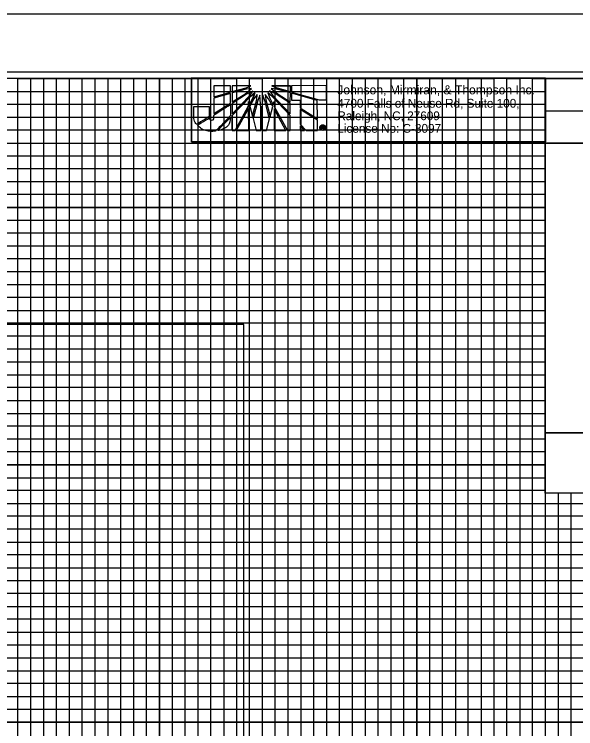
# Model space of a CAD drawing. Extents: x 1624665 to 1626605, y 896887 to 897987.
# Drawn here: x 1625926 to 1626144.2, y 897709.9 to 897987.4 of the extents above; entities that cross this region are included whole.
import ezdxf

# ---------------------------------------------------------------- set-up
doc = ezdxf.new("R2010")
doc.units = 0
for name, color, linetype in [('Default', 7, 'Continuous'), ('Prop PHM Black Shape', 7, 'Continuous'), ('Scratch_Level_1', 7, 'Continuous'), ('Sheet Cutting Line CELL', 7, 'Continuous'), ('Sheet DOT Grid CELL', 7, 'Continuous'), ('Sheet Plot Border Inside CELL', 7, 'Continuous'), ('Sheet Plot Border Outside CELL', 7, 'Continuous'), ('Sheet Profile CELL', 7, 'Continuous'), ('Sheet Profile Grid Major CELL', 7, 'Continuous'), ('Sheet Profile Grid Middle CELL', 7, 'Continuous'), ('Sheet Profile Grid Minor CELL', 7, 'Continuous'), ('Sheet Sticker Exception Certification CELL', 7, 'Continuous')]:
    doc.layers.add(name, color=color, linetype=linetype)

msp = doc.modelspace()

# ---------------------------------------------------------------- linework, layer by layer
at = {"layer": 'Default'}
for p, q in [((1626010.05, 897959.66), (1626003.61, 897959.66)), ((1626003.61, 897959.66), (1626003.62, 897955.39)), ((1626010.05, 897957.18), (1626010.05, 897959.66)), ((1626017.96, 897959.7), (1626010.72, 897959.69)), ((1626010.72, 897959.69), (1626010.72, 897957.39)), ((1626016.12, 897958.88), (1626017.96, 897959.7)), ((1626033.3, 897959.68), (1626026.16, 897959.71)), ((1626026.16, 897959.71), (1626027.97, 897958.86)), ((1626033.3, 897957.37), (1626033.3, 897959.68)), ((1626047.33, 897959.73), (1626033.8, 897959.71)), ((1626033.8, 897959.71), (1626033.8, 897957.23)), ((1626047.33, 897954.18), (1626047.33, 897959.73)), ((1626003.62, 897955.39), (1626010.05, 897957.18)), ((1626010.05, 897956.71), (1626003.62, 897954.9)), ((1626010.06, 897952.98), (1626010.05, 897956.71)), ((1626010.72, 897957.39), (1626016.12, 897958.88)), ((1626016.12, 897958.38), (1626010.72, 897956.89)), ((1626010.72, 897956.89), (1626010.72, 897953.41)), ((1626015.55, 897956.47), (1626018.22, 897958.64)), ((1626018.22, 897958.64), (1626016.12, 897958.38)), ((1626018.75, 897957.64), (1626016.3, 897956.4)), ((1626017.51, 897955.9), (1626018.75, 897957.64)), ((1626019.49, 897956.87), (1626017.79, 897955.55)), ((1626018.71, 897954.8), (1626019.49, 897956.87)), ((1626024.49, 897956.87), (1626025.27, 897954.81)), ((1626026.2, 897955.55), (1626024.49, 897956.87)), ((1626025.24, 897957.65), (1626026.48, 897955.87)), ((1626027.73, 897956.41), (1626025.24, 897957.65)), ((1626025.8, 897958.64), (1626028.5, 897956.44)), ((1626027.79, 897958.39), (1626025.8, 897958.64)), ((1626033.3, 897956.88), (1626027.79, 897958.39)), ((1626027.97, 897958.86), (1626033.3, 897957.37)), ((1626033.26, 897953.47), (1626033.3, 897956.88)), ((1626033.8, 897957.23), (1626033.8, 897957.15)), ((1626033.8, 897957.15), (1626044.45, 897954.18)), ((1626033.8, 897956.77), (1626033.8, 897956.73)), ((1626043.77, 897953.93), (1626033.8, 897956.77)), ((1626033.8, 897956.73), (1626033.8, 897954.14)), ((1626003.62, 897954.9), (1626003.62, 897948.9)), ((1626010.72, 897953.41), (1626015.55, 897956.47)), ((1626016.3, 897956.4), (1626010.73, 897952.84)), ((1626010.73, 897948.83), (1626017.51, 897955.9)), ((1626017.79, 897955.55), (1626010.73, 897948.15)), ((1626017.36, 897952.35), (1626018.71, 897954.8)), ((1626019.15, 897954.66), (1626017.54, 897951.75)), ((1626018.58, 897947.88), (1626020.24, 897954.31)), ((1626020.6, 897953.95), (1626018.79, 897946.99)), ((1626020.42, 897956.29), (1626019.15, 897954.66)), ((1626020.24, 897954.31), (1626020.42, 897956.29)), ((1626021.48, 897956.01), (1626020.6, 897953.95)), ((1626021.76, 897950.93), (1626021.48, 897956.01)), ((1626022.54, 897956.01), (1626022.22, 897950.93)), ((1626023.39, 897953.95), (1626022.54, 897956.01)), ((1626025.25, 897946.89), (1626023.39, 897953.95)), ((1626023.57, 897956.3), (1626023.79, 897954.24)), ((1626024.82, 897954.66), (1626023.57, 897956.3)), ((1626023.79, 897954.24), (1626025.46, 897947.74)), ((1626026.49, 897951.65), (1626024.82, 897954.66)), ((1626025.27, 897954.81), (1626026.66, 897952.25)), ((1626033.27, 897948.11), (1626026.2, 897955.55)), ((1626026.48, 897955.87), (1626033.26, 897948.77)), ((1626033.26, 897952.89), (1626027.73, 897956.41)), ((1626028.5, 897956.44), (1626033.26, 897953.47)), ((1626033.8, 897954.14), (1626037.1, 897954.14)), ((1626037.1, 897954.14), (1626037.11, 897951.05)), ((1626043.78, 897946.83), (1626043.77, 897953.93)), ((1626044.45, 897954.18), (1626047.33, 897954.18)), ((1626003.62, 897948.9), (1626010.06, 897952.98)), ((1626010.73, 897952.84), (1626010.73, 897948.83)), ((1626011.8, 897942.31), (1626017.05, 897951.82)), ((1626017.05, 897951.82), (1626017.04, 897953.52)), ((1626017.04, 897953.52), (1626017.36, 897952.35)), ((1626017.54, 897951.75), (1626018.58, 897947.88)), ((1626025.46, 897947.74), (1626026.49, 897951.65)), ((1626026.66, 897952.25), (1626026.98, 897953.53)), ((1626026.98, 897953.53), (1626026.99, 897951.65)), ((1626026.99, 897951.65), (1626032.13, 897942.33)), ((1626033.26, 897948.77), (1626033.26, 897952.89)), ((1626017.05, 897950.89), (1626012.3, 897942.31)), ((1626017.1, 897942.31), (1626017.05, 897950.89)), ((1626021.77, 897942.35), (1626021.76, 897950.93)), ((1626022.22, 897950.93), (1626022.23, 897942.35)), ((1626031.6, 897942.36), (1626026.99, 897950.72)), ((1626026.99, 897950.72), (1626026.99, 897942.35)), ((1626037.11, 897951.05), (1626043.78, 897946.83)), ((1626037.11, 897950.52), (1626037.11, 897944.76)), ((1626043.78, 897946.33), (1626037.11, 897950.52)), ((1626010.73, 897948.15), (1626010.73, 897942.31)), ((1626018.79, 897946.99), (1626020.01, 897942.35)), ((1626024.01, 897942.35), (1626025.25, 897946.89)), ((1626033.27, 897942.33), (1626033.27, 897948.11)), ((1626043.78, 897942.34), (1626043.78, 897946.33)), ((1626037.11, 897944.76), (1626039.42, 897942.33)), ((1626038.78, 897942.33), (1626037.11, 897944.14)), ((1626037.11, 897944.14), (1626037.12, 897942.33)), ((1626045.48, 897942.95), (1626045.48, 897943.93)), ((1626045.48, 897943.93), (1626045.88, 897943.93)), ((1626045.7, 897942.95), (1626045.48, 897942.95)), ((1626045.88, 897943.74), (1626045.7, 897943.74)), ((1626045.7, 897943.74), (1626045.7, 897943.51)), ((1626045.7, 897943.51), (1626045.88, 897943.51)), ((1626045.88, 897943.33), (1626045.7, 897943.33)), ((1626045.7, 897943.33), (1626045.7, 897942.95)), ((1626045.88, 897944.51), (1626045.88, 897944.31)), ((1626045.88, 897944.31), (1626045.88, 897944.51)), ((1626045.88, 897943.93), (1626045.88, 897943.74)), ((1626045.88, 897943.74), (1626045.88, 897943.93)), ((1626045.88, 897943.93), (1626045.94, 897943.93)), ((1626045.91, 897943.74), (1626045.88, 897943.74)), ((1626045.88, 897943.51), (1626045.88, 897943.33)), ((1626045.88, 897943.33), (1626045.88, 897943.51)), ((1626045.88, 897943.51), (1626045.89, 897943.51)), ((1626045.89, 897943.33), (1626045.88, 897943.33)), ((1626010.73, 897942.31), (1626011.8, 897942.31)), ((1626012.3, 897942.31), (1626017.1, 897942.31)), ((1626020.01, 897942.35), (1626021.77, 897942.35)), ((1626022.23, 897942.35), (1626024.01, 897942.35)), ((1626026.99, 897942.35), (1626031.6, 897942.36)), ((1626032.13, 897942.33), (1626033.27, 897942.33)), ((1626037.12, 897942.33), (1626038.78, 897942.33)), ((1626039.42, 897942.33), (1626043.78, 897942.34)), ((1626045.88, 897942.56), (1626045.88, 897942.35)), ((1626045.88, 897942.35), (1626045.88, 897942.56)), ((1626045.88, 897942.56), (1626045.89, 897942.56)), ((1626045.89, 897942.35), (1626045.88, 897942.35))]:
    msp.add_line(p, q, dxfattribs=at)
for points in [[(1625994.91, 897937.88), (1626132.43, 897937.87), (1626132.44, 897962.69), (1625994.91, 897962.7)], [(1626026.16, 897959.71), (1626033.3, 897959.68), (1626033.3, 897957.37), (1626027.97, 897958.86)], [(1626010.73, 897942.31), (1626010.73, 897948.15), (1626017.79, 897955.55), (1626019.49, 897956.87), (1626018.93, 897955.24), (1626017.36, 897952.35), (1626017.04, 897953.52), (1626017.05, 897951.82), (1626011.8, 897942.31)]]:
    msp.add_lwpolyline(points, close=True, dxfattribs=at)
for points in [[(1626003.62, 897955.39), (1626010.05, 897957.18), (1626010.05, 897959.66), (1626003.61, 897959.66), (1626003.62, 897955.39)], [(1626016.12, 897958.88), (1626017.96, 897959.7), (1626010.72, 897959.69), (1626010.72, 897957.39), (1626016.12, 897958.88)], [(1626027.97, 897958.86), (1626033.3, 897957.37), (1626033.3, 897959.68), (1626026.16, 897959.71), (1626027.97, 897958.86)], [(1626047.33, 897959.73), (1626033.8, 897959.71), (1626033.8, 897957.23), (1626033.8, 897957.15), (1626044.45, 897954.18), (1626047.33, 897954.18), (1626047.33, 897959.73)], [(1626003.62, 897948.9), (1626010.06, 897952.98), (1626010.05, 897956.71), (1626003.62, 897954.9), (1626003.62, 897948.9)], [(1626010.72, 897956.89), (1626010.72, 897953.41), (1626015.55, 897956.47), (1626018.22, 897958.64), (1626016.12, 897958.38), (1626010.72, 897956.89)], [(1626010.73, 897952.84), (1626010.73, 897948.83), (1626017.51, 897955.9), (1626018.75, 897957.64), (1626016.3, 897956.4), (1626010.73, 897952.84)], [(1626019.49, 897956.87), (1626017.79, 897955.55), (1626010.73, 897948.15), (1626010.73, 897942.31), (1626011.8, 897942.31), (1626017.05, 897951.82), (1626017.04, 897953.52), (1626017.36, 897952.35), (1626018.71, 897954.8), (1626019.49, 897956.87)], [(1626024.49, 897956.87), (1626025.27, 897954.81), (1626026.66, 897952.25), (1626026.98, 897953.53), (1626026.99, 897951.65), (1626032.13, 897942.33), (1626033.27, 897942.33), (1626033.27, 897948.11), (1626026.2, 897955.55), (1626024.49, 897956.87)], [(1626025.24, 897957.65), (1626026.48, 897955.87), (1626033.26, 897948.77), (1626033.26, 897952.89), (1626027.73, 897956.41), (1626025.24, 897957.65)], [(1626025.8, 897958.64), (1626028.5, 897956.44), (1626033.26, 897953.47), (1626033.3, 897956.88), (1626027.79, 897958.39), (1626025.8, 897958.64)], [(1626033.8, 897956.77), (1626033.8, 897956.73), (1626033.8, 897954.14), (1626037.1, 897954.14), (1626037.11, 897951.05), (1626043.78, 897946.83), (1626043.77, 897953.93), (1626033.8, 897956.77)], [(1626020.42, 897956.29), (1626019.15, 897954.66), (1626017.54, 897951.75), (1626018.58, 897947.88), (1626020.24, 897954.31), (1626020.42, 897956.29)], [(1626020.6, 897953.95), (1626018.79, 897946.99), (1626020.01, 897942.35), (1626021.77, 897942.35), (1626021.76, 897950.93), (1626021.48, 897956.01), (1626020.6, 897953.95)], [(1626022.54, 897956.01), (1626022.22, 897950.93), (1626022.23, 897942.35), (1626024.01, 897942.35), (1626025.25, 897946.89), (1626023.39, 897953.95), (1626022.54, 897956.01)], [(1626023.57, 897956.3), (1626023.79, 897954.24), (1626025.46, 897947.74), (1626026.49, 897951.65), (1626024.82, 897954.66), (1626023.57, 897956.3)], [(1626012.3, 897942.31), (1626017.1, 897942.31), (1626017.05, 897950.89), (1626012.3, 897942.31)], [(1626026.99, 897942.35), (1626031.6, 897942.36), (1626026.99, 897950.72), (1626026.99, 897942.35)], [(1626037.11, 897950.52), (1626037.11, 897944.76), (1626039.42, 897942.33), (1626043.78, 897942.34), (1626043.78, 897946.33), (1626037.11, 897950.52), (1626037.11, 897950.52)], [(1626037.12, 897942.33), (1626037.12, 897942.33), (1626038.78, 897942.33), (1626037.11, 897944.14), (1626037.12, 897942.33)], [(1626046.31, 897943.18), (1626046.31, 897943.13), (1626046.32, 897943.09), (1626046.32, 897943.05), (1626046.35, 897942.95), (1626046.14, 897942.95)]]:
    msp.add_lwpolyline(points, dxfattribs=at)
for points, degree in [([(1626001.77, 897951.66), (1626001.77, 897951.66), (1625995.82, 897951.65), (1625995.82, 897951.65), (1625995.82, 897951.65), (1625995.82, 897947.92), (1625995.82, 897947.92), (1625995.82, 897947.92), (1625995.82, 897947.53), (1625995.82, 897947.53), (1625995.82, 897946.36), (1625996.2, 897945.44), (1625996.88, 897944.66), (1625996.88, 897944.66), (1626001.78, 897947.64), (1626001.78, 897947.72), (1626001.78, 897947.72), (1626001.77, 897951.66), (1626001.77, 897951.66)], 3), ([(1626002.7, 897946.29), (1626002.32, 897946.29), (1626001.99, 897946.51), (1626001.85, 897947.22), (1626001.85, 897947.22), (1625997.23, 897944.36), (1625997.23, 897944.36), (1625998.66, 897942.86), (1626000.93, 897941.97), (1626002.85, 897941.97), (1626003.35, 897941.97), (1626003.74, 897942.02), (1626004.27, 897942.12), (1626004.27, 897942.12), (1626010.06, 897948.12), (1626010.06, 897948.12), (1626010.06, 897948.12), (1626010.06, 897952.45), (1626010.06, 897952.45), (1626010.06, 897952.45), (1626003.62, 897948.36), (1626003.62, 897948.36), (1626003.63, 897946.73), (1626003.23, 897946.3), (1626002.7, 897946.29)], 3), ([(1626002.7, 897946.29), (1626002.32, 897946.29), (1626001.99, 897946.51), (1626001.85, 897947.22), (1626001.85, 897947.22), (1625997.23, 897944.36), (1625997.23, 897944.36), (1625998.66, 897942.86), (1626000.93, 897941.97), (1626002.85, 897941.97), (1626003.35, 897941.97), (1626003.74, 897942.02), (1626004.27, 897942.12), (1626004.27, 897942.12), (1626010.06, 897948.12), (1626010.06, 897948.12), (1626010.06, 897948.12), (1626010.06, 897952.45), (1626010.06, 897952.45), (1626010.06, 897952.45), (1626003.62, 897948.36), (1626003.62, 897948.36), (1626003.63, 897946.73), (1626003.23, 897946.3), (1626002.7, 897946.29)], 3), ([(1626010.06, 897947.44), (1626010.06, 897947.44), (1626005.05, 897942.26), (1626005.05, 897942.26), (1626007.51, 897942.87), (1626009.95, 897944.5), (1626010.06, 897947.44)], 3), ([(1626045.88, 897942.35), (1626045.59, 897942.35), (1626045.33, 897942.45), (1626045.11, 897942.67), (1626044.9, 897942.87), (1626044.79, 897943.13), (1626044.79, 897943.44), (1626044.79, 897943.74), (1626044.9, 897944), (1626045.11, 897944.2), (1626045.33, 897944.4), (1626045.58, 897944.51), (1626045.88, 897944.51)], 3), ([(1626045.88, 897944.31), (1626045.64, 897944.31), (1626045.43, 897944.22), (1626045.26, 897944.06), (1626045.09, 897943.89), (1626045, 897943.68), (1626045, 897943.44), (1626045, 897943.2), (1626045.09, 897942.98), (1626045.26, 897942.81), (1626045.43, 897942.64), (1626045.64, 897942.56), (1626045.88, 897942.56)], 3), ([(1626045.88, 897944.51), (1626046.18, 897944.51), (1626046.44, 897944.4), (1626046.66, 897944.2), (1626046.87, 897944), (1626046.98, 897943.74), (1626046.98, 897943.44)], 3), ([(1626045.89, 897942.56), (1626046.13, 897942.56), (1626046.34, 897942.64), (1626046.51, 897942.81), (1626046.68, 897942.98), (1626046.77, 897943.2), (1626046.77, 897943.44), (1626046.77, 897943.68), (1626046.68, 897943.89), (1626046.51, 897944.06), (1626046.34, 897944.23), (1626046.13, 897944.31), (1626045.88, 897944.31)], 3), ([(1626045.89, 897943.51), (1626046.03, 897943.51), (1626046.1, 897943.55), (1626046.1, 897943.63), (1626046.1, 897943.71), (1626046.04, 897943.74), (1626045.91, 897943.74)], 3), ([(1626046.98, 897943.44), (1626046.98, 897943.13), (1626046.87, 897942.88), (1626046.67, 897942.66), (1626046.45, 897942.45), (1626046.19, 897942.35), (1626045.89, 897942.35)], 3), ([(1626046.06, 897943.3), (1626046.03, 897943.31), (1626045.98, 897943.33), (1626045.89, 897943.33)], 2), ([(1626045.94, 897943.93), (1626046.19, 897943.93), (1626046.32, 897943.83), (1626046.32, 897943.64), (1626046.32, 897943.55), (1626046.28, 897943.47), (1626046.2, 897943.42)], 3), ([(1626046.14, 897942.95), (1626046.11, 897943), (1626046.1, 897943.05), (1626046.1, 897943.13), (1626046.1, 897943.21), (1626046.09, 897943.27), (1626046.06, 897943.3)], 3), ([(1626046.2, 897943.42), (1626046.27, 897943.38), (1626046.3, 897943.3), (1626046.31, 897943.18)], 2)]:
    msp.add_open_spline(points, degree=degree, dxfattribs=at)
at = {"layer": 'Prop PHM Black Shape'}
msp.add_lwpolyline([(1625994.91, 897962.7), (1626132.43, 897962.7), (1626132.43, 897937.87), (1625994.91, 897937.87)], close=True, dxfattribs=at)
at = {"layer": 'Scratch_Level_1'}
msp.add_lwpolyline([(1625682.2, 897612.11), (1626015.27, 897612.11), (1626015.27, 897866.93), (1625682.2, 897866.93)], close=True, dxfattribs=at)
at = {"layer": 'Sheet Cutting Line CELL'}
msp.add_line((1626349.4, 897987.44), (1624665.4, 897987.44), dxfattribs=at)
at = {"layer": 'Sheet DOT Grid CELL'}
for p, q in [((1625932.4, 897462.44), (1625932.4, 897962.44)), ((1625982.4, 897462.44), (1625982.4, 897962.44)), ((1626032.4, 897462.44), (1626032.4, 897962.44)), ((1626082.4, 897462.44), (1626082.4, 897962.44)), ((1626132.35, 897912.44), (1624832.4, 897912.44)), ((1626132.35, 897862.44), (1624832.4, 897862.44)), ((1626132.4, 897462.44), (1626132.4, 897824.89)), ((1626132.4, 897812.44), (1624832.4, 897812.44)), ((1626332.4, 897762.44), (1624832.4, 897762.44)), ((1626332.4, 897712.44), (1624832.4, 897712.44))]:
    msp.add_line(p, q, dxfattribs=at)
at = {"layer": 'Sheet Plot Border Inside CELL'}
msp.add_lwpolyline([(1624678.4, 896909.89), (1626344.9, 896909.89), (1626344.9, 897964.99), (1624678.4, 897964.99)], close=True, dxfattribs=at)
at = {"layer": 'Sheet Plot Border Outside CELL'}
msp.add_lwpolyline([(1624665.4, 896887.44), (1626349.4, 896887.44), (1626349.4, 897987.44), (1624665.4, 897987.44)], close=True, dxfattribs=at)
at = {"layer": 'Sheet Profile CELL'}
msp.add_line((1626132.35, 897949.89), (1626332.4, 897949.89), dxfattribs=at)
for points in [[(1626332.4, 897962.44), (1624832.4, 897962.44), (1624832.4, 896912.44), (1626332.4, 896912.44)], [(1626132.35, 897962.44), (1626332.4, 897962.44), (1626332.4, 897937.39), (1626132.35, 897937.39)], [(1626132.35, 897937.39), (1626232.4, 897937.39), (1626232.4, 897824.89), (1626132.35, 897824.89)]]:
    msp.add_lwpolyline(points, close=True, dxfattribs=at)
at = {"layer": 'Sheet Profile Grid Major CELL'}
for points in [[(1625582.4, 897462.44), (1625632.4, 897462.44), (1625632.4, 897962.44), (1625682.4, 897962.44), (1625682.4, 897462.44), (1625732.4, 897462.44), (1625732.4, 897962.44), (1625782.4, 897962.44), (1625782.4, 897462.44), (1625832.4, 897462.44), (1625832.4, 897962.44), (1625882.4, 897962.44), (1625882.4, 897462.44), (1625932.4, 897462.44), (1625932.4, 897962.44), (1625982.4, 897962.44), (1625982.4, 897462.44), (1626032.4, 897462.44), (1626032.4, 897962.44), (1626082.4, 897962.44), (1626082.4, 897462.44), (1626132.4, 897462.44), (1626132.4, 897962.44), (1626158.7, 897962.44)], [(1624832.4, 897912.44), (1626132.4, 897912.44)], [(1626132.4, 897862.44), (1624832.4, 897862.44), (1624832.4, 897812.44), (1626132.4, 897812.44)], [(1626332.4, 897762.44), (1624832.4, 897762.44), (1624832.4, 897712.44), (1626332.4, 897712.44)]]:
    msp.add_lwpolyline(points, dxfattribs=at)
at = {"layer": 'Sheet Profile Grid Middle CELL'}
msp.add_line((1624832.4, 897937.44), (1626132.35, 897937.44), dxfattribs=at)
for points in [[(1625607.4, 897462.44), (1625657.4, 897462.44), (1625657.4, 897962.44), (1625707.4, 897962.44), (1625707.4, 897462.44), (1625757.4, 897462.44), (1625757.4, 897962.44), (1625807.4, 897962.44), (1625807.4, 897462.44), (1625857.4, 897462.44), (1625857.4, 897962.44), (1625907.4, 897962.44), (1625907.4, 897462.44), (1625957.4, 897462.44), (1625957.4, 897962.44), (1626007.4, 897962.44), (1626007.4, 897462.44), (1626057.4, 897462.44), (1626057.4, 897962.44), (1626107.4, 897962.44), (1626107.4, 897462.44), (1626157.4, 897462.44), (1626157.4, 897801.39)], [(1626132.4, 897887.44), (1624832.4, 897887.44), (1624832.4, 897837.44), (1626132.4, 897837.44)], [(1626332.4, 897787.44), (1624832.4, 897787.44), (1624832.4, 897737.44), (1626157.4, 897737.44)]]:
    msp.add_lwpolyline(points, dxfattribs=at)
at = {"layer": 'Sheet Profile Grid Minor CELL'}
for p, q in [((1624882.4, 897957.44), (1626132.4, 897957.44)), ((1626132.4, 897952.44), (1624882.4, 897952.09)), ((1624882.4, 897947.44), (1626132.4, 897947.44)), ((1626132.35, 897827.44), (1624882.4, 897827.44)), ((1626132.4, 897822.44), (1624882.4, 897822.44)), ((1626132.4, 897817.44), (1624882.4, 897817.44)), ((1624882.4, 897807.44), (1626132.4, 897807.44)), ((1626132.4, 897802.44), (1624882.4, 897802.44)), ((1624882.4, 897797.44), (1626282.4, 897797.44)), ((1626282.4, 897777.44), (1624882.4, 897777.44)), ((1624882.4, 897772.44), (1626282.4, 897772.44)), ((1626282.4, 897752.44), (1624882.4, 897752.44)), ((1624882.4, 897747.44), (1626282.4, 897747.44)), ((1626282.4, 897727.44), (1624882.4, 897727.44)), ((1624882.4, 897722.44), (1626282.4, 897722.44)), ((1626282.4, 897717.44), (1624882.4, 897717.44))]:
    msp.add_line(p, q, dxfattribs=at)
for points in [[(1625927.4, 897462.44), (1625927.4, 897962.44), (1625937.4, 897962.44), (1625937.4, 897462.44)], [(1625942.4, 897462.44), (1625942.4, 897962.44), (1625947.4, 897962.44), (1625947.4, 897462.44)], [(1625952.4, 897462.44), (1625952.4, 897962.44), (1625962.4, 897962.44), (1625962.4, 897462.44)], [(1625967.4, 897462.44), (1625967.4, 897962.44), (1625972.4, 897962.44), (1625972.4, 897462.44)], [(1625977.4, 897462.44), (1625977.4, 897962.44), (1625987.4, 897962.44), (1625987.4, 897462.44)], [(1625992.4, 897462.44), (1625992.4, 897962.44), (1625997.4, 897962.44), (1625997.4, 897462.44)], [(1626002.4, 897462.44), (1626002.4, 897962.44), (1626012.4, 897962.44), (1626012.4, 897462.44)], [(1626017.4, 897462.44), (1626017.4, 897962.44), (1626022.4, 897962.44), (1626022.4, 897462.44)], [(1626027.4, 897462.44), (1626027.4, 897962.44), (1626037.4, 897962.44), (1626037.4, 897462.44)], [(1626042.4, 897462.44), (1626042.4, 897962.44), (1626047.4, 897962.44), (1626047.4, 897462.44)], [(1626052.4, 897462.44), (1626052.4, 897962.44), (1626062.4, 897962.44), (1626062.4, 897462.44)], [(1626067.4, 897462.44), (1626067.4, 897962.44), (1626072.4, 897962.44), (1626072.4, 897462.44)], [(1626077.4, 897462.44), (1626077.4, 897962.44), (1626087.4, 897962.44), (1626087.4, 897462.44)], [(1626092.4, 897462.44), (1626092.4, 897962.44), (1626097.4, 897962.44), (1626097.4, 897462.44)], [(1626102.4, 897462.44), (1626102.4, 897962.44), (1626112.4, 897962.44), (1626112.4, 897462.44)], [(1626117.4, 897462.44), (1626117.4, 897962.44), (1626122.4, 897962.44), (1626122.4, 897462.44)], [(1626127.4, 897462.44), (1626127.4, 897962.44), (1626137.4, 897962.44)], [(1626132.4, 897942.44), (1624882.4, 897942.44), (1624882.4, 897932.44), (1626132.4, 897932.44)], [(1626132.35, 897927.44), (1624882.4, 897927.44), (1624882.4, 897922.44), (1626132.4, 897922.44)], [(1626132.4, 897917.44), (1624882.4, 897917.44), (1624882.4, 897907.44), (1626132.4, 897907.44)], [(1626132.4, 897902.44), (1624882.4, 897902.44), (1624882.4, 897897.44), (1626132.4, 897897.44)], [(1626132.4, 897892.44), (1624882.4, 897892.44), (1624882.4, 897882.44), (1626132.4, 897882.44)], [(1626132.4, 897877.44), (1624882.4, 897877.44), (1624882.4, 897872.44), (1626132.4, 897872.44)], [(1626132.4, 897867.44), (1624882.4, 897867.44), (1624882.4, 897857.44), (1626132.4, 897857.44)], [(1626132.4, 897852.34), (1624882.5, 897852.34), (1624882.5, 897847.44), (1626132.4, 897847.44)], [(1626132.4, 897842.44), (1624882.4, 897842.44), (1624882.4, 897832.44), (1626132.4, 897832.44)], [(1626137.4, 897801.39), (1626137.4, 897462.44), (1626142.4, 897462.44), (1626142.4, 897801.39)], [(1626282.4, 897792.44), (1624882.4, 897792.44), (1624882.4, 897782.44), (1626282.4, 897782.44)], [(1626282.4, 897767.44), (1624882.4, 897767.44), (1624882.4, 897757.44), (1626282.4, 897757.44)], [(1626282.4, 897742.44), (1624882.4, 897742.44), (1624882.4, 897732.44), (1626282.4, 897732.44)]]:
    msp.add_lwpolyline(points, dxfattribs=at)
at = {"layer": 'Sheet Sticker Exception Certification CELL'}
for p, q in [((1626132.35, 897801.39), (1626132.35, 897824.89)), ((1626132.35, 897824.89), (1626332.39, 897824.89)), ((1626132.35, 897801.39), (1626132.35, 897824.89)), ((1626132.35, 897824.89), (1626332.39, 897824.89)), ((1626332.39, 897801.39), (1626132.35, 897801.39)), ((1626332.39, 897801.39), (1626132.35, 897801.39))]:
    msp.add_line(p, q, dxfattribs=at)

# ---------------------------------------------------------------- texts
at = {"layer": 'Default'}
for s, height, p in [('Johnson, Mirmiran, & Thompson Inc.', 3.5139, (1626051.55, 897956.34)), ('4700 Falls of Neuse Rd, Suite 100, ', 3.4135, (1626051.55, 897951.18)), ('Raleigh, NC, 27609', 3.4135, (1626051.55, 897946.31)), ('License No: C-3097', 3.4135, (1626051.54, 897941.43))]:
    msp.add_text(s, height=height, rotation=359.9946, dxfattribs=at).set_placement(p)

doc.saveas('drawing.dxf')
